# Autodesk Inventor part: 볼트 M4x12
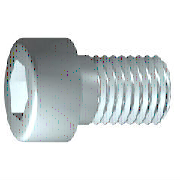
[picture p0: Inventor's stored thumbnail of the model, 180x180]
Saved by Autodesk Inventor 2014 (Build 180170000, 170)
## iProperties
IsCustomPart: 0
Created: 2015-12
Part Number: 볼트 M4x12
Material: 강철, 연강
Description: 6각머리 태핑 나사
Document SubType Name: Modeling
Standard: KS B 1003
Designer: mdu
Standards Organization: KS
Language: ko-KR
Size Designation: M 4 x 12
Categories: <MemberInstance><Categories><Category DisplayName="조임쇠" InternalName="e4da775c-781d-43d5-af7c-5136215cf5a6" Mnemonic="FSTN"><Category DisplayName="볼트" InternalN
Density: 7.86 g/cm^3
Mass: 2.23465 g
Surface Area: 3.30853 cm^2
Volume: 0.284306 cm^3
Appearance: 진녹색
Author: mdu
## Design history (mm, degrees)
sketch "스케치1"
  geometry: L1 (-1, 0)-(12, 0); L2 (12, 0)-(12, 2); L3 (12, 2)-(1.75, 2); L4 (1.75, 2)-(1.32, 2); L5 (1.32, 2)-(0, 2); L6 (0, 2)-(0, 3.5); L7 (0, 3.5)-(-4, 3.5); L8 (-4, 3.5)-(-4, 1.732); L9 (-4, 1.732)-(-2, 1.732); L10 (-2, 1.732)-(-1, 0); L11 (-7.2, 0)-(15.2, 0) reference; L12 (0, -0.7)-(0, 4.2) reference; L13 (1.75, 2)-(0, 2)
  constraints: 22 end point, 6 parallel, 2 collinear, 2 perpendicular, 1 horizontal, 1 point on line
  dimensions: "d1" = 10.25 distance from line of L3.end L2 (= GEL); "d2" = 0.42952 distance of L4.end L3.end (computed from GAL); "d3" = 4 distance between parallel lines of L8 L6 (= KOH); "d4" = 2 distance of L8.end L9.end (= INTI); "d5" = 60 deg angle of L10 L1; "d6" = 4 diameter of L3 L1 (= GD); "d7" = 4 diameter of L5 L1 (= BDM); "d8" = 3.4641 diameter of L9 L1 (= 1.1547 x SW); "d9" = 7 diameter of L7 L1 (= KOD); "d26" = 12 distance between parallel lines of L12 L2 (= NLG)
revolve "본체" sketch "스케치1" stored, may be unused: angle "d10" = 90 deg
sketch "스케치2"
  geometry: L1 (0, -4.9)-(0, 4.9) reference; L2 (-4.9, 0)-(4.9, 0) reference; L3 (1.732, 0)-(0.866, -1.5); L4 (0.866, -1.5)-(-0.866, -1.5); L5 (-0.866, -1.5)-(-1.732, 0); L6 (-1.732, 0)-(-0.866, 1.5); L7 (-0.866, 1.5)-(0.866, 1.5); L8 (0.866, 1.5)-(1.732, 0); 2 further points
  constraints: 12 end point, 1 coincident, 1 horizontal alignment, 1 point on line, 12 other
extrude "슬롯" join sketch "스케치2" stored distance "d11" = 10; taper "d12" = 0 deg
workplane "Work Plane1"
fillet "Fillet2" dims "d30" = 0.1 (= R)
body "Solid1"
fillet "모깎기1" dims "d17" = 0.4 (= RR)
feature "스레드" dims "d13" = 10.25 (= GEL), "d14" = 0
chamfer "모따기1" distance "d15" = 0.42941 (= -0.5 x SPD + 0.5 x GD); stored, may be unused: second distance "d16" = 0.42941 (= GUL), angle "d27" = 45 deg
other parameters: "GD" = 4 (= NND) [user parameter; used in 2 equation terms], "NLG" = 12 [user parameter; used in 1 equation term], "GEL" = 10.25 [user parameter; used in 2 equation terms], "KOD" = 7 [user parameter; used in 1 equation term], "KOH" = 4 [user parameter; used in 1 equation term], "INTI" = 2 [user parameter; used in 1 equation term], "GAL" = 0.42941 (= 0.61345 x PTC) [user parameter; used in 1 equation term], "GUL" = 0.42941 (= 0.61345 x PTC) [user parameter; used in 1 equation term], "BDM" = 4 (= NND) [user parameter; used in 1 equation term], "SW" = 3 [user parameter; used in 2 equation terms], "RR" = 0.4 [user parameter; used in 1 equation term], "SPD" = 3.14117 (= NND - 1.2269 x PTC) [user parameter; used in 1 equation term], "d19" = 0, "d28" = 0, "d29" = 0, "R" = 0.1 [user parameter; used in 1 equation term], "PHH" = 0.2 [user parameter], "GD1" = 3.14117 (= THREADDIA - 1.2269 x PTC) [user parameter], "THREADDIA" = 4 [user parameter; used in 1 equation term], "FAWI" = 45 deg [user parameter], "TPU" = 14.28571 (computed from PTC) [user parameter], "PTC" = 0.7 [user parameter; used in 5 equation terms], "NND" = 4 [user parameter; used in 3 equation terms], "TOA" = 30 deg [user parameter], "E0" = 3.465 (= 1.155 x SW) [user parameter]
